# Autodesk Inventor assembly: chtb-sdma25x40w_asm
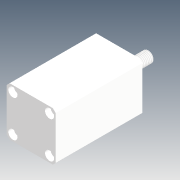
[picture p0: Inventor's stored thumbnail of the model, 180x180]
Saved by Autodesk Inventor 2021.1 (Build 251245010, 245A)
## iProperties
Company: Microsoft
Created: 2018-05
Part Number: chtb-sdma25x40w_asm
Description: STEP AP214
Document SubType Name: Assembly
Designer: user
Title: chtb-sdma25x40w_asm.STEP
Author: Windows
Revision Number: ÈÎºÎ
Sending System: SolidWorks 2015
Preprocessor: SwSTEP 2.0
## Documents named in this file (4)
- D:\Vault_2016\Projekty\Clamptek\Hydraulic\CHTB\CHTB-25\Inventor\chtb-sdma25x40w\chtb-sdma25x40w_asm.iam
- D:\Vault_2016\Projekty\Clamptek\Hydraulic\CHTB\CHTB-25\Inventor\chtb-sdma25x40w\CHTB-25QG.ipt
- D:\Vault_2016\Projekty\Clamptek\Hydraulic\CHTB\CHTB-25\Inventor\chtb-sdma25x40w\CHTB-SDMA25X40NBT.ipt
- D:\Vault_2016\Projekty\Clamptek\Hydraulic\CHTB\CHTB-25\Inventor\chtb-sdma25x40w\CHTB-SDMA25X40WHSG.ipt
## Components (3 placed, 3 different names)
1. CHTB-25QG_1
2. CHTB-SDMA25X40NBT_2
3. CHTB-SDMA25X40WHSG_3
